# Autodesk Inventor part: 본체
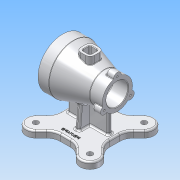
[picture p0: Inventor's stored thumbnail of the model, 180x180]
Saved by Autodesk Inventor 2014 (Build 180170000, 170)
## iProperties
Created: 2018-03
Part Number: 본체
Material: 알루미늄 6061
Document SubType Name: Modeling
Designer: 703
Density: 2.71 g/cm^3
Appearance: 알루미늄 - 평지
Mass: 1018.73 g
Surface Area: 857.088 cm^2
Volume: 375.915 cm^3
Author: 703
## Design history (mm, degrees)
sketch "스케치1"
  geometry: L1 (-50, 0)-(50, 0); L2 (-50, 0)-(-50, 45); L3 (-50, 45)-(-30, 45); L4 (-30, 45)-(27, 27.5); L5 (27, 27.5)-(50, 27.5); L6 (50, 27.5)-(50, 0); 2 further points
  constraints: 12 end point, 2 parallel, 2 perpendicular, 1 coincident, 1 horizontal, 1 midpoint
  dimensions: "d0" = 100 distance of L1.start L1.end; "d1" = 90 diameter of L3 L1; "d2" = 77 horizontal distance of L4.end L2.end; "d3" = 55 diameter of L5 L1; "d4" = 20 distance of L2.end L3.end
revolve "회전1" sketch "스케치1" stored, may be unused: angle "d5" = 90 deg
node "작업 평면1"
sketch "스케치2"
  geometry: L1 (9.189, -45)-(-9.189, -45); L2 (-45, -9.189)-(-45, 9.189); L3 (-9.189, 45)-(9.189, 45); L4 (45, 9.189)-(45, -9.189); L5 (45, -45)-(-45, 45); L6 (-45, -45)-(45, 45); L7 (0, 0)-(-49.497, 49.497); L8 (-26.866, 52.322)-(-36.77, 62.225); L9 (-62.225, 36.77)-(-52.322, 26.866); L10 (0, 0)-(49.497, 49.497); L11 (52.322, 26.866)-(62.225, 36.77); L12 (36.77, 62.225)-(26.866, 52.322); L13 (0, 0)-(-49.497, -49.497); L14 (-52.322, -26.866)-(-62.225, -36.77); L15 (-36.77, -62.225)-(-26.866, -52.322); L16 (0, 0)-(49.497, -49.497); L17 (26.866, -52.322)-(36.77, -62.225); L18 (62.225, -36.77)-(52.322, -26.866); C1 r 5 at (-49.497, 49.497); C2 r 5 at (-49.497, -49.497); C3 r 5 at (49.497, -49.497); C4 r 5 at (49.497, 49.497); A1 r 18 centre (0, 0) between (-12.728, -12.728) and (12.728, 12.728); A2 r 18 centre (-49.497, 49.497) between (-36.77, 62.225) and (-62.225, 36.77); A3 r 18 centre (0, 0) between (-12.728, 12.728) and (12.728, -12.728); A4 r 18 centre (49.497, 49.497) between (62.225, 36.77) and (36.77, 62.225); A5 r 18 centre (0, 0) between (12.728, -12.728) and (-12.728, 12.728); A6 r 18 centre (-49.497, -49.497) between (-62.225, -36.77) and (-36.77, -62.225); A7 r 18 centre (0, 0) between (12.728, 12.728) and (-12.728, -12.728); A8 r 18 centre (49.497, -49.497) between (36.77, -62.225) and (62.225, -36.77); A9 r 25 centre (-70, 9.189) between (-45, 9.189) and (-52.322, 26.866); A10 r 25 centre (-70, -9.189) between (-52.322, -26.866) and (-45, -9.189); A11 r 25 centre (-9.189, -70) between (-9.189, -45) and (-26.866, -52.322); A12 r 25 centre (9.189, -70) between (26.866, -52.322) and (9.189, -45); A13 r 25 centre (70, -9.189) between (45, -9.189) and (52.322, -26.866); A14 r 25 centre (70, 9.189) between (52.322, 26.866) and (45, 9.189); A15 r 25 centre (9.189, 70) between (9.189, 45) and (26.866, 52.322); A16 r 25 centre (-9.189, 70) between (-26.866, 52.322) and (-9.189, 45); 5 further points
  constraints: 44 end point, 32 point on circle, 32 tangent, 20 centre point, 19 point on line, 7 equal radius, 7 midpoint, 6 parallel, 5 coincident, 3 perpendicular, 1 horizontal
  dimensions: "d7" = 90 distance of L5.end L6.end; "d8" = 90 distance of L6.start L5.end; "d10" = 36 diameter of A2; "d11" = 36 diameter of A4; "d12" = 36 diameter of A6; "d13" = 36 diameter of A8; "d14" = 25 radius of A9; "d15" = 10 diameter of C1; "d16" = 10 diameter of C2; "d17" = 10 diameter of C3; "d18" = 10 diameter of C4; "d19" = 70 distance of point (0, 0) C1.centre; "d20" = 70 distance of point (0, 0) L13.end; "d21" = 70 distance of point (0, 0) L16.end; "d22" = 70 distance of point (0, 0) L10.end
extrude "돌출1" join sketch "스케치2" distance "d23" = 12; taper "d24" = 0 deg
sketch "스케치3"
  geometry: L1 (37, -4)-(-37, -4); L2 (-37, -4)-(-37, 4); L3 (-37, 4)-(37, 4); L4 (37, 4)-(37, -4); L5 (37, -4)-(-37, 4); L6 (-37, -4)-(37, 4); 1 further point
  constraints: 12 end point, 2 midpoint, 2 parallel, 1 horizontal, 1 perpendicular
  dimensions: "d25" = 74 distance of L2.end L3.end; "d26" = 8 distance of L1.end L2.end
extrude "돌출2" join sketch "스케치3" stored distance "d27" = 12; taper "d28" = 0 deg
sketch "스케치4"
  geometry: L1 (-45, -82)-(-45, -70) reference; L2 (-45, -70)-(-4, -70) reference; L3 (-4, -70)-(-4, -35.565) reference; L4 (4, -35.565)-(4, -70) reference; L5 (4, -70)-(45, -70) reference; L6 (45, -70)-(45, -82) reference; L7 (45, -82)-(-45, -82) reference; L8 (-9.189, -70)-(9.189, -70) reference; L9 (0, -70)-(24, -70); L10 (24, -70)-(19.991, -24.175); L11 (0, -70)-(-24, -70); L12 (-24, -70)-(-19.991, -24.175); L13 (-19.991, -24.175)-(19.991, -24.175); A1 r 35.789 centre (0, 0) between (4, -35.565) and (-4, -35.565) reference; 1 further point
  constraints: 10 end point, 2 point on line, 1 midpoint
  dimensions: "d29" = 24 distance of L9.start L9.end; "d30" = 46 distance of L9.end L10.end; "d31" = 85 deg angle of L10 L9; "d32" = 24 distance of L9.start L11.end; "d33" = 46 distance of L11.end L12.end; "d34" = 85 deg angle of L11 L12
extrude "돌출3" join sketch "스케치4" stored distance "d35" = 8; taper "d36" = 0 deg
sketch "스케치5"
  geometry: L1 (-50, 27.5)-(-27, 27.5) reference; L2 (-27, 27.5)-(30, 45) reference; L3 (30, 45)-(50, 45) reference; L4 (50, 45)-(50, -45) reference; L5 (50, -45)-(37, -45) reference; L6 (37, -45)-(37, -70) reference; L7 (37, -70)-(45, -70) reference; L8 (45, -70)-(45, -82) reference; L9 (45, -82)-(-45, -82) reference; L10 (-45, -82)-(-45, -70) reference; L11 (-45, -70)-(-37, -70) reference; L12 (-37, -70)-(-37, -27.5) reference; L13 (-37, -27.5)-(-50, -27.5) reference; L14 (-50, -27.5)-(-50, 27.5) reference; L15 (50, 0)-(-50, 0); L16 (-50, 27.5)-(-50, -27.5) reference; L17 (50, 0)-(50, 35); L18 (50, 45)-(50, -45) reference; L19 (50, 35)-(30, 35); L20 (27, 32)-(27, 29); L21 (30, 45)-(30, -44.822) reference; L22 (24, 26)-(-17, 26); L23 (-20, 23)-(-20, 23); L24 (-23, 20)-(-50, 20); L25 (-50, 0)-(-50, 20); A1 r 3 centre (30, 32) between (30, 35) and (27, 32); A2 r 3 centre (24, 29) between (24, 26) and (27, 29); A3 r 3 centre (-17, 23) between (-17, 26) and (-20, 23); A4 r 3 centre (-23, 23) between (-23, 20) and (-20, 23); 4 further points
  constraints: 16 end point, 8 point on circle, 8 point on line, 8 tangent, 4 centre point, 4 parallel, 3 equal radius, 2 midpoint, 1 collinear, 1 perpendicular
  dimensions: "d37" = 70 diameter of L19 L15; "d38" = 52 diameter of L22 L15; "d39" = 40 diameter of L24 L15; "d40" = 23 distance of L17.end point (27, 35); "d41" = 47 distance of point (27, 26) point (-20, 26); "d42" = 3 radius of A1
revolve "회전2" sketch "스케치5" stored, may be unused: angle "d43" = 90 deg
node "작업 평면2"
sketch "스케치6"
  geometry: L1 (4.5, -12.5)-(-4.5, -12.5); L2 (-12.5, -4.5)-(-12.5, 4.5); L3 (-4.5, 12.5)-(4.5, 12.5); L4 (12.5, 4.5)-(12.5, -4.5); L5 (12.5, -12.5)-(-12.5, 12.5); L6 (-12.5, -12.5)-(12.5, 12.5); A1 r 8 centre (-4.5, 4.5) between (-4.5, 12.5) and (-12.5, 4.5); A2 r 8 centre (-4.5, -4.5) between (-12.5, -4.5) and (-4.5, -12.5); A3 r 8 centre (4.5, -4.5) between (4.5, -12.5) and (12.5, -4.5); A4 r 8 centre (4.5, 4.5) between (12.5, 4.5) and (4.5, 12.5); 1 further point
  constraints: 12 end point, 8 point on circle, 8 point on line, 8 tangent, 4 centre point, 3 equal radius, 2 midpoint, 2 parallel, 1 horizontal, 1 perpendicular
  dimensions: "d45" = 25 distance of L5.end L6.end; "d46" = 25 distance of L6.start L5.end; "d47" = 8 radius of A1
extrude "돌출4" join sketch "스케치6" stored distance "d48" = 8; taper "d49" = 0 deg
sketch "스케치7"
  geometry: L1 (4.5, -7.5)-(-4.5, -7.5); L2 (-7.5, -4.5)-(-7.5, 4.5); L3 (-4.5, 7.5)-(4.5, 7.5); L4 (7.5, 4.5)-(7.5, -4.5); L5 (7.5, -7.5)-(-7.5, 7.5); L6 (-7.5, -7.5)-(7.5, 7.5); A1 r 3 centre (-4.5, 4.5) between (-4.5, 7.5) and (-7.5, 4.5); A2 r 3 centre (-4.5, -4.5) between (-7.5, -4.5) and (-4.5, -7.5); A3 r 3 centre (4.5, -4.5) between (4.5, -7.5) and (7.5, -4.5); A4 r 3 centre (4.5, 4.5) between (7.5, 4.5) and (4.5, 7.5); 1 further point
  constraints: 12 end point, 8 point on circle, 8 point on line, 8 tangent, 4 centre point, 3 equal radius, 2 midpoint, 2 parallel, 1 horizontal, 1 perpendicular
  dimensions: "d50" = 15 distance of L5.end L6.end; "d51" = 15 distance of L6.start L5.end; "d52" = 3 radius of A1
extrude "돌출5" cut sketch "스케치7" distance "d53" = 30; taper "d54" = 0 deg
fillet "모깎기1" dims "d55" = 1
sketch "스케치8"
  geometry: C1 r 35 at (0, 0) reference; 6 further points
  constraints: 1 horizontal alignment, 7 other
  dimensions: "d56" = 40 distance of C1.centre point (40, 0); "d59" = 360 deg dimension on C1.centre point (40, 0) (derived)
hole "구멍1" sketch "스케치8" at (40, 0), (20, 34.641), (-20, 34.641), (-40, 0), (-20, -34.641), (20, -34.641) diameter "d61" = 3.242; stored, may be unused: countersink angle "d65" = 90 deg, drill point angle "d67" = 118 deg; dims "d62" = 9, "d63" = 4, "d64" = 2, "d66" = 11
sketch "스케치9"
  geometry: L1 (0, 0)-(-27.5, 0); L2 (0, 0)-(13.75, -23.816); L3 (0, 0)-(27.5, 0); L4 (0, 0)-(13.75, 23.816); L5 (0, 0)-(27.5, 0); C1 r 27.5 at (0, 0); A1 r 27.5 centre (0, 0) between (7.292, -26.516) and (19.317, -19.573) reference; A2 r 7 centre (-27.5, 0) between (-26.609, 6.943) and (-26.609, -6.943); A3 r 7 centre (13.75, -23.816) between (7.292, -26.516) and (19.317, -19.573); A4 r 7 centre (13.75, 23.816) between (19.317, 19.573) and (7.292, 26.516)
  constraints: 12 point on circle, 10 end point, 4 centre point, 4 coincident, 3 horizontal, 2 equal length
  dimensions: "d68" = 55 diameter of C1; "d69" = 27.5 distance of L1.start L1.end; "d70" = 27.5 distance of L1.start L2.end; "d71" = 60 deg angle of L2 L3; "d72" = 27.5 distance of L1.start L4.end; "d73" = 60 deg angle of L5 L4; "d74" = 14 diameter of A2; "d75" = 14 diameter of A3; "d76" = 14 diameter of A4
extrude "돌출6" join sketch "스케치9" distance "d77" = 15; taper "d78" = 0 deg
sketch "스케치10"
  geometry: A1 r 7 centre (0, 0) between (0.891, 6.943) and (0.891, -6.943) reference; A2 r 7 centre (41.25, -23.816) between (34.792, -26.516) and (46.817, -19.573) reference; A3 r 7 centre (41.25, 23.816) between (46.817, 19.573) and (34.792, 26.516) reference; 3 further points
  constraints: 3 coincident
hole "구멍2" sketch "스케치10" at (0, 0), (41.25, -23.816), (41.25, 23.816) diameter "d79" = 3.242; stored, may be unused: countersink angle "d83" = 90 deg, drill point angle "d85" = 118 deg; dims "d80" = 9, "d81" = 4, "d82" = 2, "d84" = 11
fillet "모깎기2" dims "d86" = 3
fillet "모깎기3" dims "d87" = 1
fillet "모깎기4" dims "d88" = 3
chamfer "모따기1" distance "d89" = 1; stored, may be unused: second distance "d90" = 2, angle "d91" = 45 deg
chamfer "모따기2" distance "d92" = 1; stored, may be unused: second distance "d93" = 2, angle "d94" = 45 deg
fillet "모깎기5" dims "d95" = 3
fillet "모깎기6" dims "d96" = 3
fillet "모깎기7" dims "d97" = 3
sketch "스케치11"
  geometry: L1 (45, -9.189)-(45, 9.189) reference; 2 further points
  constraints: 1 other
  dimensions: "d98" = 45 distance from line of L1 point (0, -35); "d99" = 35 distance of point (0, -35) point (0, 0)
feature "엠보싱1" sketch "스케치11" dims "d0" = 100, "d1" = 90, "d2" = 77, "d3" = 55, "d4" = 20, "d7" = 90, "d8" = 90, "d10" = 36, "d11" = 36, "d12" = 36, "d13" = 36, "d14" = 25, "d15" = 10, "d16" = 10, "d17" = 10, "d18" = 10, "d19" = 70, "d20" = 70, "d21" = 70, "d22" = 70, "d100" = 0.5, "d101" = 0
node "솔리드1"
node "절단 모서리 투영1"
node "절단 모서리 투영2"
other parameters: "d6" = -82, "d44" = 45
